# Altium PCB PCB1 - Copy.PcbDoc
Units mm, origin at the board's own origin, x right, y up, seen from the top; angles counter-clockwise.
Board outline 152.4 x 101.6 mm, 2 copper layers (Top Layer, Bottom Layer); 6 components, 0 nets, 33 pads, 0 vias.
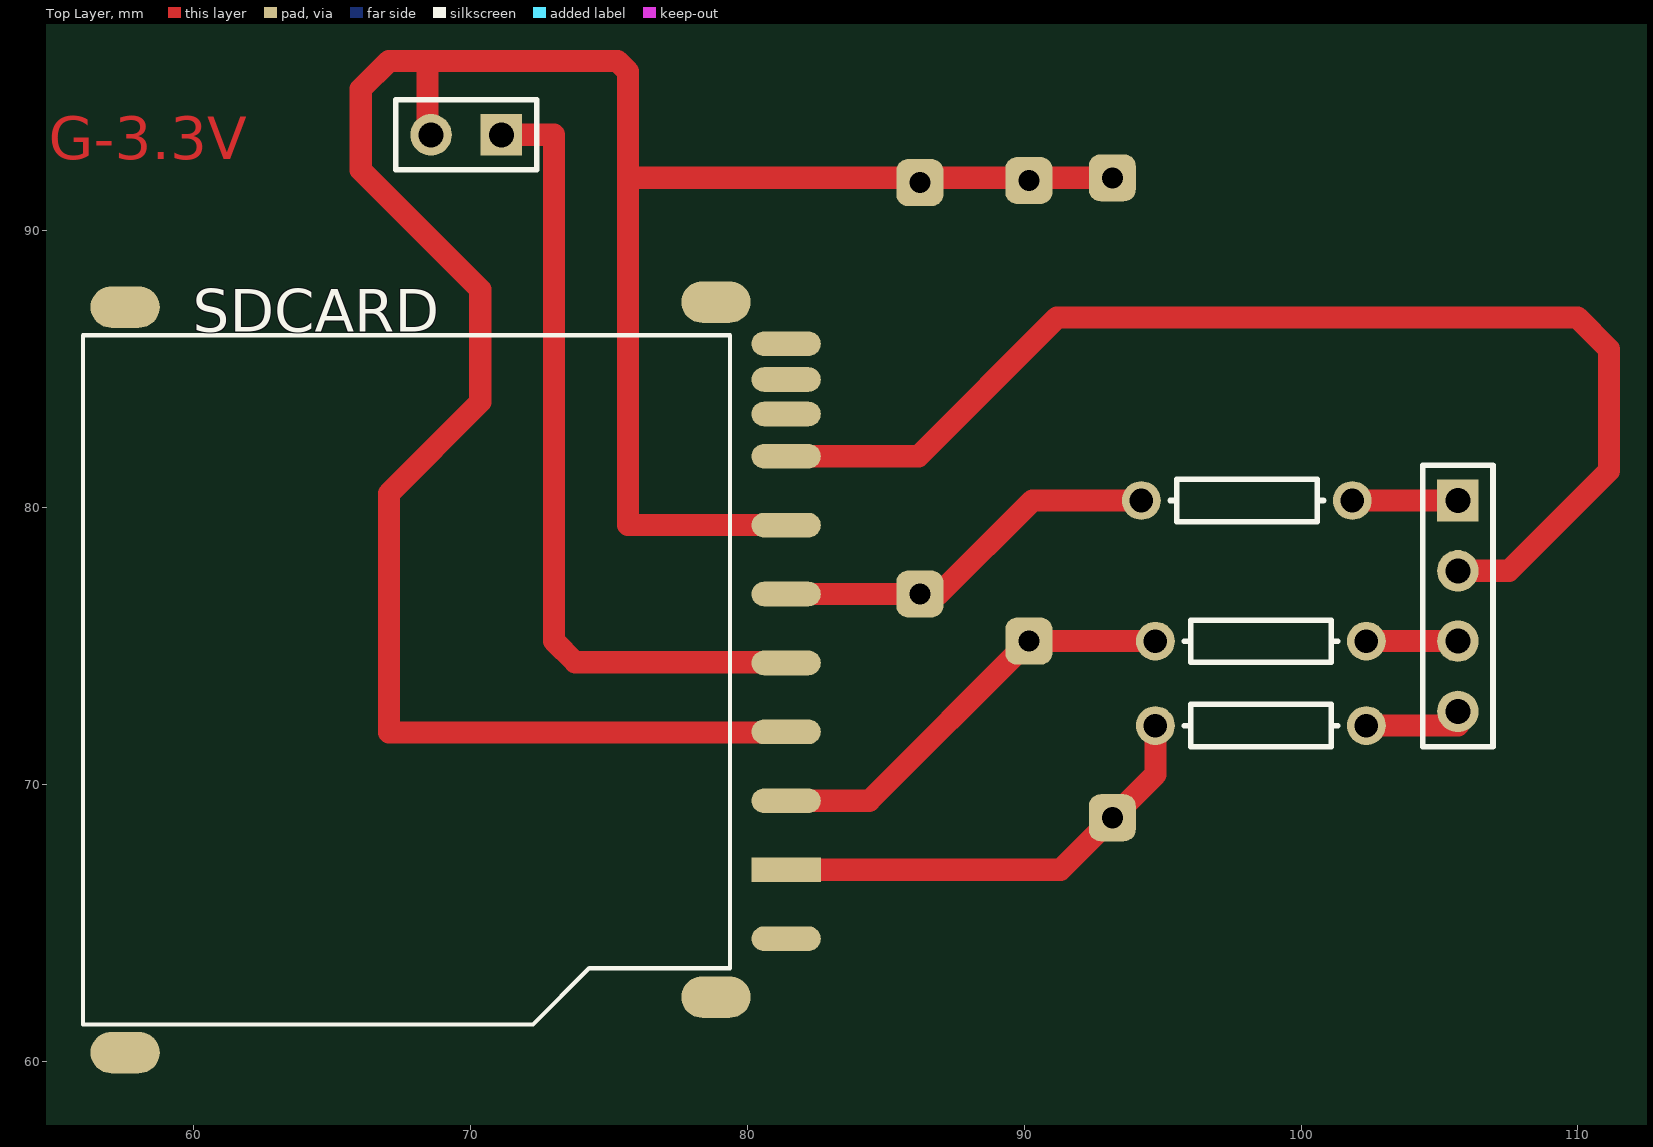
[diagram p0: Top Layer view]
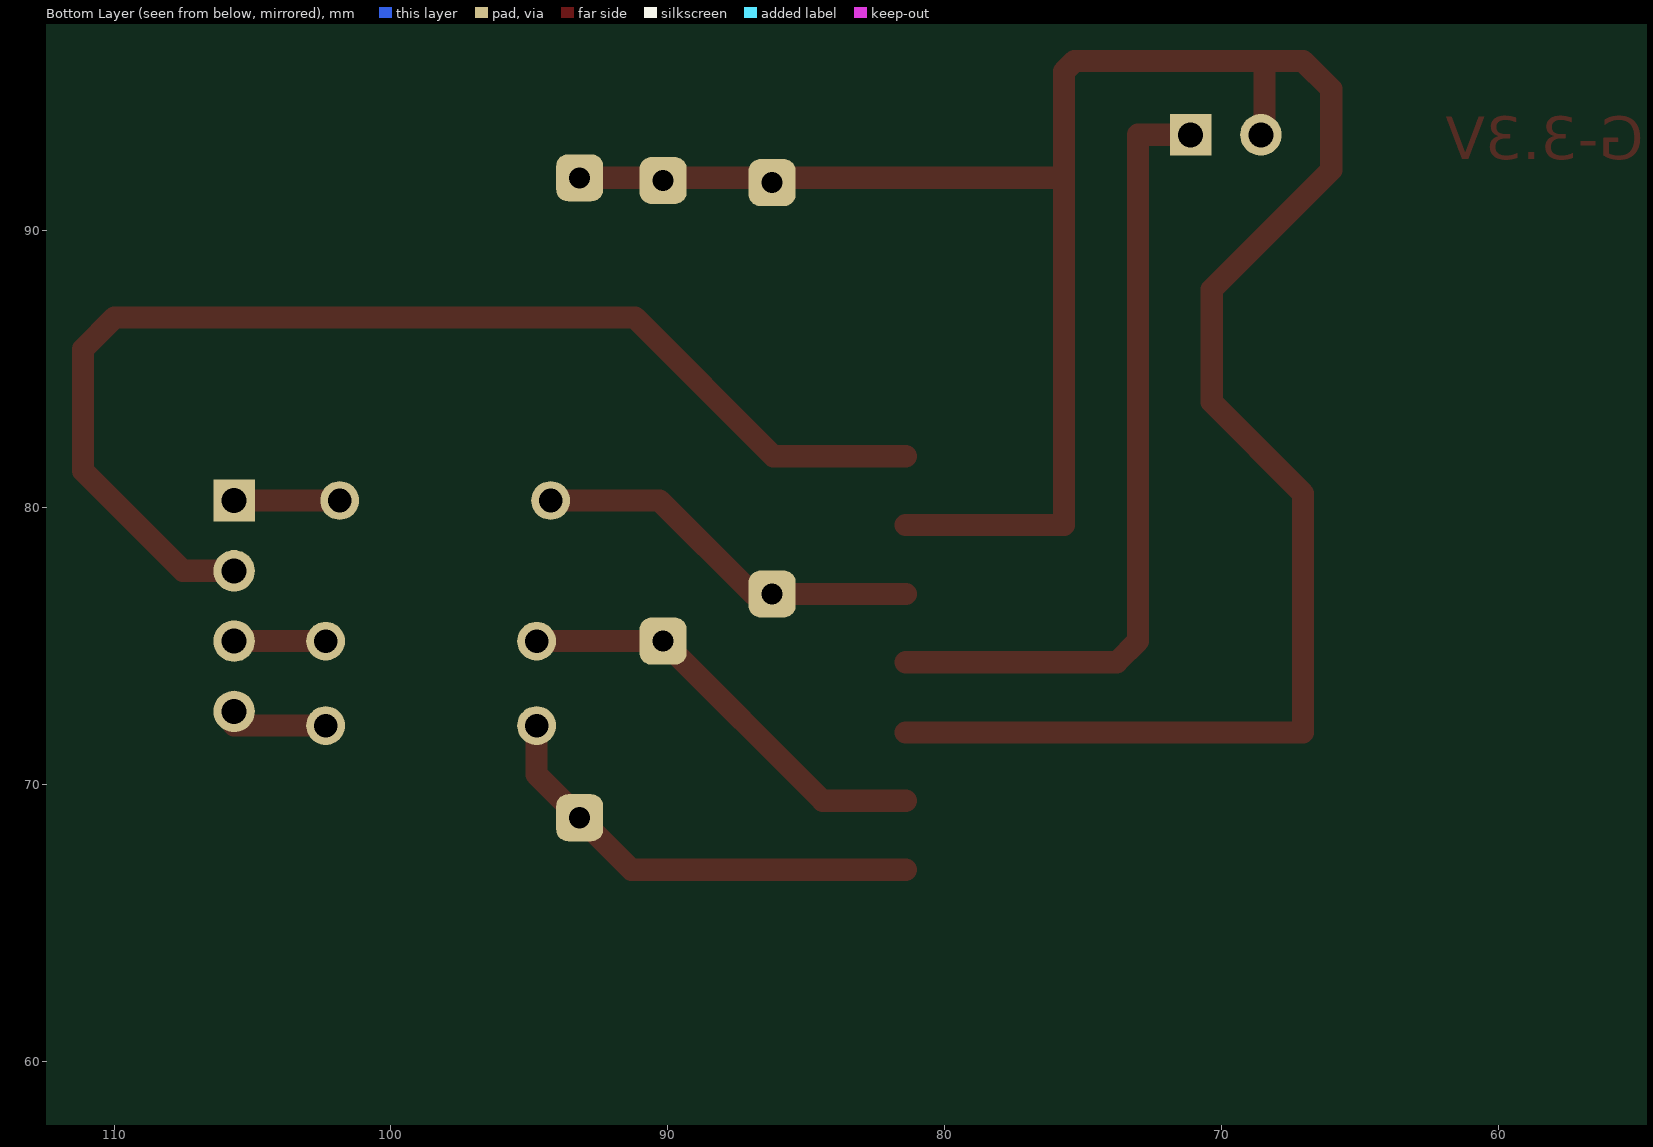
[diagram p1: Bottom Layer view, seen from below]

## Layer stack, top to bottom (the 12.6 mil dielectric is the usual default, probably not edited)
Top Layer: signal copper 0.0356
Dielectric: dielectric 0.32, FR-4, Dk 4.8
Bottom Layer: signal copper 0.0356

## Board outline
25.4,25.4 177.8,25.4 177.8,127 25.4,127

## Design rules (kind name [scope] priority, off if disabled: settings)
Clearance [All] p1: gap=0.254
PolygonConnect [All] p1: connectstyle=Relief reliefconductorwidth=0.254 reliefentries=4 polygonreliefangle="90 Angle"
RoutingVias [All] p1: holewidth=0.711 width=1.27 viastyle="Through Hole" minholewidth=0.711 minwidth=1.27 maxholewidth=0.711 maxwidth=1.27
SilkscreenOverComponentPads [All] p1: minsilkscreentomaskgap=0.254
SolderMaskExpansion [All] p1: expansion=0.102
TestPointUsage [All] p1: valid=0 allowmultiple=FALSE
Testpoint [All] p1: side=15 testpointundercomponent=TRUE minsize=1.016 maxsize=2.54 preferedsize=1.524 minholesize=0 maxholesize=1.016 preferedholesize=0.813 testpointgrid=0.025 style=1023 order=0123456789
Width [All] p1: maxlimit=0.6 minlimit=0.254 preferedwidth=0.5
23 further rules are at their usual default settings.

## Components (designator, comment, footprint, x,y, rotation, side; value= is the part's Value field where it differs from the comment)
SDCARD "SDCARD" SDCARD 81.407,66.929 r180 top
? "Comment" AXIAL-0.3 98.552,72.136 r0 top
? "Comment" AXIAL-0.3 98.552,75.184 r0 top
? "Comment" AXIAL-0.3 98.044,80.264 r0 top
? "Comment" HDR1X4 105.664,80.264 r270 top
? "Comment" HDR1X2 71.12,93.472 r180 top

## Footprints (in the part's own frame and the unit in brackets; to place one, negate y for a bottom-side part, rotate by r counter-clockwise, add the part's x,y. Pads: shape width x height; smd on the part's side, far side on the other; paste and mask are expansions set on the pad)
AXIAL-0.3 [mm] "Resistor; 2 Leads"
  round 1.4 hole 0.85: 1(-3.81,0) 2(3.81,0)
  silkscreen extent -2.77,-0.76 2.77,0.76
HDR1X2 [mm] "Connector; Header; 2 Position"
  rect 1.5x1.5 hole 0.9: 1(0,0)
  round 1.5 hole 0.9: 2(2.54,0)
  silkscreen extent -1.27,-1.27 3.81,1.27
HDR1X4 [mm] "Connector; Header; 4 Position"
  rect 1.5x1.5 hole 0.9: 1(0,0)
  round 1.5 hole 0.9: 2(2.54,0) 3(5.08,0) 4(7.62,0)
  silkscreen extent -1.27,-1.27 8.89,1.27
SDCARD [mil]
  rect 98.43x35 smd: 1(0,0)
  oval 98.43x35 smd: 2(0,-98) 3(0,-196) 4(0,-294) 5(0,-392) 6(0,-490) 7(0,-588) 8(0,-648) 9(0,98) 10(0,-697) 12(0,-748)
  oval 98.43x59.06 smd: 11(100,181.1) 11(100,-807.09) 11(940,260) 11(940,-800)
  silkscreen extent 80,-760 1000,220

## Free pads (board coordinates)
  rrect50% 1.7x1.7 hole 0.762: 6(90.17,75.184) 7(93.184,68.805) 8(86.233,76.886) 9(86.233,91.745) 10(90.17,91.821) 11(93.184,91.919)

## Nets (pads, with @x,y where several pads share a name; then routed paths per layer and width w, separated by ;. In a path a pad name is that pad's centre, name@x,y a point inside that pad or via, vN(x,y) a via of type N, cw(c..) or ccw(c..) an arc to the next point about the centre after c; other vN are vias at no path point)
pads on no net: ?.1 ?.2 ?.3 ?.4 SDCARD.1 SDCARD.2 SDCARD.3 SDCARD.4 SDCARD.5 SDCARD.6 SDCARD.7 SDCARD.8 SDCARD.9 SDCARD.10 SDCARD.11 SDCARD.12
copper on no net: | length 224.4
  Top Layer w0.254: 68.453,93.472 68.58,93.472 ; 81.407,72.009 81.407,71.907 ; 81.407,74.397 81.509,74.295 ; 81.407,79.248 81.407,79.375 ; 81.407,79.502 81.407,79.375 ; 81.534,79.248 81.407,79.375 ; 81.407,71.907 81.407,71.882 81.407,71.907
  Top Layer w0.6: 75.692,91.919 75.692,92.329 ; 81.407,74.397 81.407,74.422 ; 105.664,72.136 105.664,72.644
  Top Layer w0.8: 68.453,93.472 68.453,96.139 ; 71.12,93.472 73.025,93.472 73.025,75.184 73.787,74.422 81.407,74.422 ; 75.692,91.919 93.184,91.919 ; 81.407,66.929 91.308,66.929 94.742,70.363 94.742,72.136 ; 81.407,69.418 84.404,69.418 90.17,75.184 94.742,75.184 ; 81.407,71.882 67.056,71.882 67.056,80.518 70.358,83.82 70.358,87.884 66.04,92.202 66.04,95.123 67.056,96.139 68.453,96.139 ; 81.407,76.886 86.919,76.886 90.297,80.264 94.234,80.264 ; 81.407,79.375 75.692,79.375 75.692,95.758 75.311,96.139 68.453,96.139 ; 81.407,81.864 86.182,81.864 91.186,86.868 109.982,86.868 111.125,85.725 111.125,81.341 107.508,77.724 105.664,77.724 ; 101.854,80.264 105.664,80.264 ; 102.362,72.136 105.664,72.136 ; 102.362,75.184 105.664,75.184

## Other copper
Top Layer:
  text "GNG-3.3V" at 51.562,92.583 h1.52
